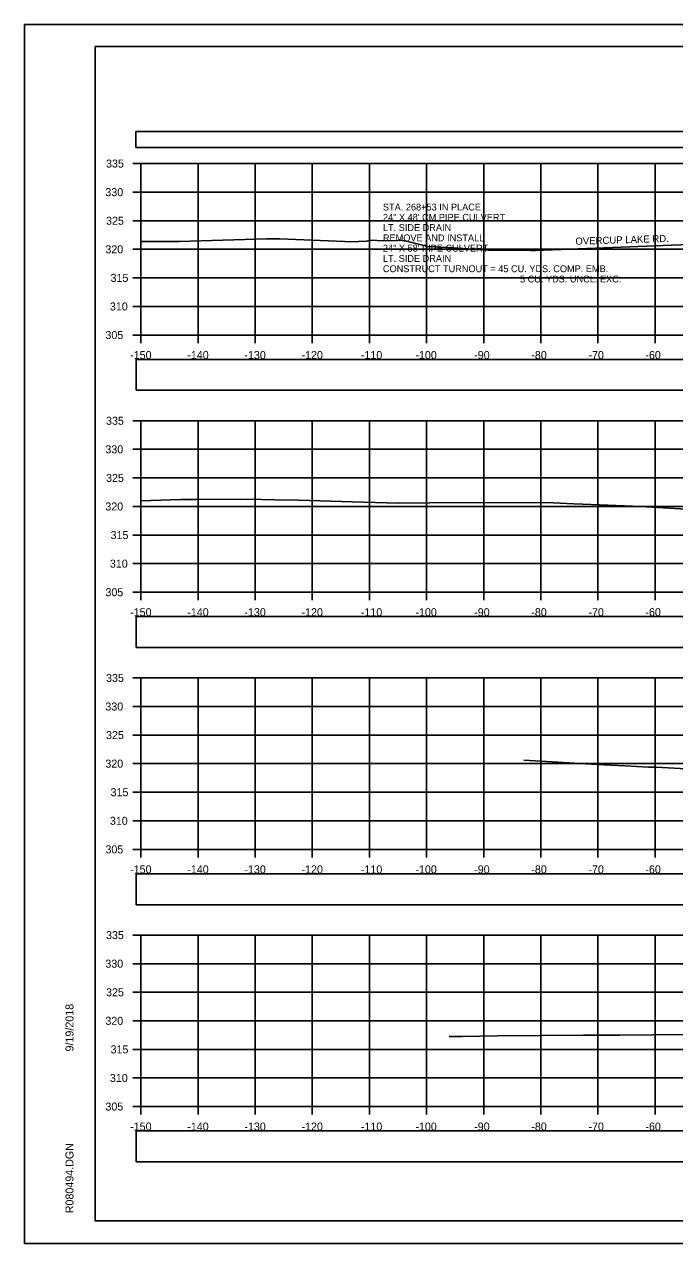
# Model space of a CAD drawing. Extents: x 1376273 to 1384221, y 378927 to 384592.
# Drawn here: x 1380021.2 to 1380135.1, y 383098.6 to 383311.9 of the extents above; entities that cross this region are included whole.
import ezdxf

# ---------------------------------------------------------------- set-up
doc = ezdxf.new("R2010")
doc.units = 0
for name, color, linetype in [('R_Axis', 7, 'Continuous'), ('R_Axis Annot', 7, 'Continuous'), ('R_Border', 7, 'Continuous'), ('R_Drive', 7, 'Continuous'), ('R_Exist Surface', 7, 'Continuous'), ('R_Grid', 7, 'Continuous'), ('R_No Plot', 7, 'Continuous')]:
    doc.layers.add(name, color=color, linetype=linetype)

msp = doc.modelspace()

# ---------------------------------------------------------------- linework, layer by layer
at = {"layer": 'R_Axis'}
for p, q in [((1380040.26, 383287.55), (1380041.66, 383287.55)), ((1380041.66, 383257.55), (1380041.66, 383287.55)), ((1380040.26, 383282.55), (1380041.66, 383282.55)), ((1380040.26, 383277.55), (1380041.66, 383277.55)), ((1380040.26, 383272.55), (1380041.66, 383272.55)), ((1380040.26, 383267.55), (1380041.66, 383267.55)), ((1380040.26, 383262.55), (1380041.66, 383262.55)), ((1380040.26, 383257.55), (1380041.66, 383257.55)), ((1380041.66, 383257.55), (1380341.66, 383257.55)), ((1380041.66, 383256.15), (1380041.66, 383257.55)), ((1380051.66, 383256.15), (1380051.66, 383257.55)), ((1380061.66, 383256.15), (1380061.66, 383257.55)), ((1380071.66, 383256.15), (1380071.66, 383257.55)), ((1380081.66, 383256.15), (1380081.66, 383257.55)), ((1380091.66, 383256.15), (1380091.66, 383257.55)), ((1380101.66, 383256.15), (1380101.66, 383257.55)), ((1380111.66, 383256.15), (1380111.66, 383257.55)), ((1380121.66, 383256.15), (1380121.66, 383257.55)), ((1380131.66, 383256.15), (1380131.66, 383257.55)), ((1380040.26, 383242.55), (1380041.66, 383242.55)), ((1380041.66, 383212.55), (1380041.66, 383242.55)), ((1380040.26, 383237.55), (1380041.66, 383237.55)), ((1380040.26, 383232.55), (1380041.66, 383232.55)), ((1380040.26, 383227.55), (1380041.66, 383227.55)), ((1380040.26, 383222.55), (1380041.66, 383222.55)), ((1380040.26, 383217.55), (1380041.66, 383217.55)), ((1380040.26, 383212.55), (1380041.66, 383212.55)), ((1380041.66, 383212.55), (1380341.66, 383212.55)), ((1380041.66, 383211.15), (1380041.66, 383212.55)), ((1380051.66, 383211.15), (1380051.66, 383212.55)), ((1380061.66, 383211.15), (1380061.66, 383212.55)), ((1380071.66, 383211.15), (1380071.66, 383212.55)), ((1380081.66, 383211.15), (1380081.66, 383212.55)), ((1380091.66, 383211.15), (1380091.66, 383212.55)), ((1380101.66, 383211.15), (1380101.66, 383212.55)), ((1380111.66, 383211.15), (1380111.66, 383212.55)), ((1380121.66, 383211.15), (1380121.66, 383212.55)), ((1380131.66, 383211.15), (1380131.66, 383212.55)), ((1380040.26, 383197.55), (1380041.66, 383197.55)), ((1380041.66, 383167.55), (1380041.66, 383197.55)), ((1380040.26, 383192.55), (1380041.66, 383192.55)), ((1380040.26, 383187.55), (1380041.66, 383187.55)), ((1380040.26, 383182.55), (1380041.66, 383182.55)), ((1380040.26, 383177.55), (1380041.66, 383177.55)), ((1380040.26, 383172.55), (1380041.66, 383172.55)), ((1380040.26, 383167.55), (1380041.66, 383167.55)), ((1380041.66, 383167.55), (1380341.66, 383167.55)), ((1380041.66, 383166.15), (1380041.66, 383167.55)), ((1380051.66, 383166.15), (1380051.66, 383167.55)), ((1380061.66, 383166.15), (1380061.66, 383167.55)), ((1380071.66, 383166.15), (1380071.66, 383167.55)), ((1380081.66, 383166.15), (1380081.66, 383167.55)), ((1380091.66, 383166.15), (1380091.66, 383167.55)), ((1380101.66, 383166.15), (1380101.66, 383167.55)), ((1380111.66, 383166.15), (1380111.66, 383167.55)), ((1380121.66, 383166.15), (1380121.66, 383167.55)), ((1380131.66, 383166.15), (1380131.66, 383167.55)), ((1380040.26, 383152.55), (1380041.66, 383152.55)), ((1380041.66, 383122.55), (1380041.66, 383152.55)), ((1380040.26, 383147.55), (1380041.66, 383147.55)), ((1380040.26, 383142.55), (1380041.66, 383142.55)), ((1380040.26, 383137.55), (1380041.66, 383137.55)), ((1380040.26, 383132.55), (1380041.66, 383132.55)), ((1380040.26, 383127.55), (1380041.66, 383127.55)), ((1380040.26, 383122.55), (1380041.66, 383122.55)), ((1380041.66, 383122.55), (1380341.66, 383122.55)), ((1380041.66, 383121.15), (1380041.66, 383122.55)), ((1380051.66, 383121.15), (1380051.66, 383122.55)), ((1380061.66, 383121.15), (1380061.66, 383122.55)), ((1380071.66, 383121.15), (1380071.66, 383122.55)), ((1380081.66, 383121.15), (1380081.66, 383122.55)), ((1380091.66, 383121.15), (1380091.66, 383122.55)), ((1380101.66, 383121.15), (1380101.66, 383122.55)), ((1380111.66, 383121.15), (1380111.66, 383122.55)), ((1380121.66, 383121.15), (1380121.66, 383122.55)), ((1380131.66, 383121.15), (1380131.66, 383122.55))]:
    msp.add_line(p, q, dxfattribs=at)
at = {"layer": 'R_Axis Annot'}
for points in [[(1380040.77, 383290.34), (1380342.57, 383290.34), (1380342.57, 383293.15), (1380040.77, 383293.15)], [(1380040.81, 383247.88), (1380342.5, 383247.88), (1380342.5, 383253.29), (1380040.81, 383253.29)], [(1380040.81, 383202.87), (1380342.5, 383202.87), (1380342.5, 383208.28), (1380040.81, 383208.28)], [(1380040.81, 383157.87), (1380342.5, 383157.87), (1380342.5, 383163.28), (1380040.81, 383163.28)], [(1380040.81, 383112.89), (1380342.5, 383112.89), (1380342.5, 383118.3), (1380040.81, 383118.3)]]:
    msp.add_lwpolyline(points, close=True, dxfattribs=at)
at = {"layer": 'R_Border'}
for p, q in [((1380033.66, 383308.01), (1380349.84, 383308.01)), ((1380033.66, 383102.55), (1380033.66, 383308.01)), ((1380033.66, 383102.55), (1380033.66, 383102.55)), ((1380349.84, 383102.55), (1380033.66, 383102.55))]:
    msp.add_line(p, q, dxfattribs=at)
at = {"layer": 'R_Exist Surface'}
for points in [[(1380041.66, 383273.9), (1380044.66, 383273.94), (1380048.35, 383273.93), (1380063.63, 383274.37), (1380064.07, 383274.38), (1380065.91, 383274.4), (1380077.34, 383273.91), (1380078.34, 383273.87), (1380081.13, 383273.99), (1380081.88, 383274.13), (1380084.14, 383274.01), (1380086.61, 383274.09), (1380086.92, 383274.13), (1380088.12, 383273.98), (1380091.87, 383273.03), (1380095.41, 383272.86), (1380102.52, 383272.4), (1380104.64, 383272.39), (1380109.94, 383272.35), (1380110.57, 383272.35), (1380110.76, 383272.35), (1380130.23, 383273.07), (1380134.48, 383273.3), (1380137.89, 383273.37)], [(1380041.66, 383228.51), (1380048.57, 383228.77), (1380051.37, 383228.77), (1380060.31, 383228.82), (1380065.16, 383228.73), (1380069.28, 383228.64), (1380078.64, 383228.34), (1380086.77, 383228.11), (1380092.25, 383228.21), (1380110.35, 383228.25), (1380113.85, 383228.17), (1380117.44, 383228.02), (1380123.44, 383227.8), (1380129.16, 383227.56), (1380139.04, 383226.95)], [(1380108.7, 383183.17), (1380121.52, 383182.43), (1380126.45, 383182.16), (1380130.53, 383181.95), (1380131.87, 383181.95), (1380146.62, 383181.13)], [(1380095.63, 383134.81), (1380097.85, 383134.78), (1380104.07, 383134.95), (1380119.15, 383135.02), (1380125.52, 383135.04), (1380142.92, 383135.2)]]:
    msp.add_lwpolyline(points, dxfattribs=at)
at = {"layer": 'R_Grid'}
for p, q in [((1380041.66, 383287.55), (1380341.66, 383287.55)), ((1380041.66, 383257.55), (1380041.66, 383287.55)), ((1380051.66, 383257.55), (1380051.66, 383287.55)), ((1380061.66, 383257.55), (1380061.66, 383287.55)), ((1380071.66, 383257.55), (1380071.66, 383287.55)), ((1380081.66, 383257.55), (1380081.66, 383287.55)), ((1380091.66, 383257.55), (1380091.66, 383287.55)), ((1380101.66, 383257.55), (1380101.66, 383287.55)), ((1380111.66, 383257.55), (1380111.66, 383287.55)), ((1380121.66, 383257.55), (1380121.66, 383287.55)), ((1380131.66, 383257.55), (1380131.66, 383287.55)), ((1380041.66, 383282.55), (1380341.66, 383282.55)), ((1380041.66, 383277.55), (1380341.66, 383277.55)), ((1380041.66, 383272.55), (1380341.66, 383272.55)), ((1380041.66, 383267.55), (1380341.66, 383267.55)), ((1380041.66, 383262.55), (1380341.66, 383262.55)), ((1380041.66, 383257.55), (1380341.66, 383257.55)), ((1380041.66, 383242.55), (1380341.66, 383242.55)), ((1380041.66, 383212.55), (1380041.66, 383242.55)), ((1380051.66, 383212.55), (1380051.66, 383242.55)), ((1380061.66, 383212.55), (1380061.66, 383242.55)), ((1380071.66, 383212.55), (1380071.66, 383242.55)), ((1380081.66, 383212.55), (1380081.66, 383242.55)), ((1380091.66, 383212.55), (1380091.66, 383242.55)), ((1380101.66, 383212.55), (1380101.66, 383242.55)), ((1380111.66, 383212.55), (1380111.66, 383242.55)), ((1380121.66, 383212.55), (1380121.66, 383242.55)), ((1380131.66, 383212.55), (1380131.66, 383242.55)), ((1380041.66, 383237.55), (1380341.66, 383237.55)), ((1380041.66, 383232.55), (1380341.66, 383232.55)), ((1380041.66, 383227.55), (1380341.66, 383227.55)), ((1380041.66, 383222.55), (1380341.66, 383222.55)), ((1380041.66, 383217.55), (1380341.66, 383217.55)), ((1380041.66, 383212.55), (1380341.66, 383212.55)), ((1380041.66, 383197.55), (1380341.66, 383197.55)), ((1380041.66, 383167.55), (1380041.66, 383197.55)), ((1380051.66, 383167.55), (1380051.66, 383197.55)), ((1380061.66, 383167.55), (1380061.66, 383197.55)), ((1380071.66, 383167.55), (1380071.66, 383197.55)), ((1380081.66, 383167.55), (1380081.66, 383197.55)), ((1380091.66, 383167.55), (1380091.66, 383197.55)), ((1380101.66, 383167.55), (1380101.66, 383197.55)), ((1380111.66, 383167.55), (1380111.66, 383197.55)), ((1380121.66, 383167.55), (1380121.66, 383197.55)), ((1380131.66, 383167.55), (1380131.66, 383197.55)), ((1380041.66, 383192.55), (1380341.66, 383192.55)), ((1380041.66, 383187.55), (1380341.66, 383187.55)), ((1380041.66, 383182.55), (1380341.66, 383182.55)), ((1380041.66, 383177.55), (1380341.66, 383177.55)), ((1380041.66, 383172.55), (1380341.66, 383172.55)), ((1380041.66, 383167.55), (1380341.66, 383167.55)), ((1380041.66, 383152.55), (1380341.66, 383152.55)), ((1380041.66, 383122.55), (1380041.66, 383152.55)), ((1380051.66, 383122.55), (1380051.66, 383152.55)), ((1380061.66, 383122.55), (1380061.66, 383152.55)), ((1380071.66, 383122.55), (1380071.66, 383152.55)), ((1380081.66, 383122.55), (1380081.66, 383152.55)), ((1380091.66, 383122.55), (1380091.66, 383152.55)), ((1380101.66, 383122.55), (1380101.66, 383152.55)), ((1380111.66, 383122.55), (1380111.66, 383152.55)), ((1380121.66, 383122.55), (1380121.66, 383152.55)), ((1380131.66, 383122.55), (1380131.66, 383152.55)), ((1380041.66, 383147.55), (1380341.66, 383147.55)), ((1380041.66, 383142.55), (1380341.66, 383142.55)), ((1380041.66, 383137.55), (1380341.66, 383137.55)), ((1380041.66, 383132.55), (1380341.66, 383132.55)), ((1380041.66, 383127.55), (1380341.66, 383127.55)), ((1380041.66, 383122.55), (1380341.66, 383122.55))]:
    msp.add_line(p, q, dxfattribs=at)
at = {"layer": 'R_No Plot'}
for p, q in [((1380021.26, 383311.9), (1380354.59, 383311.9)), ((1380021.26, 383098.57), (1380354.59, 383098.57))]:
    msp.add_line(p, q, dxfattribs=at)
for points in [[(1380021.25, 383311.9), (1380354.59, 383311.9), (1380354.59, 383098.57), (1380021.25, 383098.57)], [(1380267.58, 383308.01), (1380267.58, 383298.13), (1380303.31, 383298.13), (1380303.31, 383295.21), (1380326.51, 383295.21), (1380326.51, 383270.88), (1380349.84, 383270.88), (1380349.84, 383102.55), (1380033.66, 383102.55), (1380033.66, 383308.01)]]:
    msp.add_lwpolyline(points, close=True, dxfattribs=at)

# ---------------------------------------------------------------- texts
at = {"layer": 'R_Axis Annot'}
for s, height, p in [('335', 1.4, (1380035.55, 383286.85)), ('330', 1.4, (1380035.43, 383281.85)), ('STA. 268+53 IN PLACE', 1.2, (1380084.02, 383279.34)), ('325', 1.4, (1380035.55, 383276.85)), ('24" X 48\' CM PIPE CULVERT', 1.2, (1380084.02, 383277.55)), ('LT. SIDE DRAIN', 1.2, (1380084.02, 383275.75)), ('REMOVE AND INSTALL', 1.2, (1380084.02, 383273.95)), ('320', 1.4, (1380035.43, 383271.85)), ('24" X 58\' PIPE CULVERT', 1.2, (1380084.02, 383272.15)), ('CONSTRUCT TURNOUT = 45 CU. YDS. COMP. EMB.', 1.2, (1380084.02, 383268.55)), ('LT. SIDE DRAIN', 1.2, (1380084.02, 383270.35)), ('315', 1.4, (1380036.34, 383266.85)), ('5 CU. YDS. UNCL. EXC.', 1.2, (1380108.02, 383266.75)), ('310', 1.4, (1380036.22, 383261.85)), ('305', 1.4, (1380035.44, 383256.85)), ('-150', 1.4, (1380039.77, 383253.35)), ('-140', 1.4, (1380049.77, 383253.35)), ('-130', 1.4, (1380059.77, 383253.35)), ('-120', 1.4, (1380069.77, 383253.35)), ('-110', 1.4, (1380080.16, 383253.35)), ('-100', 1.4, (1380089.71, 383253.35)), ('-90', 1.4, (1380100, 383253.35)), ('-80', 1.4, (1380110, 383253.35)), ('-70', 1.4, (1380120, 383253.35)), ('-60', 1.4, (1380129.97, 383253.35)), ('335', 1.4, (1380035.55, 383241.85)), ('330', 1.4, (1380035.43, 383236.85)), ('325', 1.4, (1380035.55, 383231.85)), ('320', 1.4, (1380035.43, 383226.85)), ('315', 1.4, (1380036.34, 383221.85)), ('310', 1.4, (1380036.22, 383216.85)), ('305', 1.4, (1380035.44, 383211.85)), ('-150', 1.4, (1380039.77, 383208.35)), ('-140', 1.4, (1380049.77, 383208.35)), ('-130', 1.4, (1380059.77, 383208.35)), ('-120', 1.4, (1380069.77, 383208.35)), ('-110', 1.4, (1380080.16, 383208.35)), ('-100', 1.4, (1380089.71, 383208.35)), ('-90', 1.4, (1380100, 383208.35)), ('-80', 1.4, (1380110, 383208.35)), ('-70', 1.4, (1380120, 383208.35)), ('-60', 1.4, (1380129.97, 383208.35)), ('335', 1.4, (1380035.55, 383196.85)), ('330', 1.4, (1380035.43, 383191.85)), ('325', 1.4, (1380035.55, 383186.85)), ('320', 1.4, (1380035.43, 383181.85)), ('315', 1.4, (1380036.34, 383176.85)), ('310', 1.4, (1380036.22, 383171.85)), ('305', 1.4, (1380035.44, 383166.85)), ('-150', 1.4, (1380039.77, 383163.35)), ('-140', 1.4, (1380049.77, 383163.35)), ('-130', 1.4, (1380059.77, 383163.35)), ('-120', 1.4, (1380069.77, 383163.35)), ('-110', 1.4, (1380080.16, 383163.35)), ('-100', 1.4, (1380089.71, 383163.35)), ('-90', 1.4, (1380100, 383163.35)), ('-80', 1.4, (1380110, 383163.35)), ('-70', 1.4, (1380120, 383163.35)), ('-60', 1.4, (1380129.97, 383163.35)), ('335', 1.4, (1380035.55, 383151.85)), ('330', 1.4, (1380035.43, 383146.85)), ('325', 1.4, (1380035.55, 383141.85)), ('320', 1.4, (1380035.43, 383136.85)), ('315', 1.4, (1380036.34, 383131.85)), ('310', 1.4, (1380036.22, 383126.85)), ('305', 1.4, (1380035.44, 383121.85)), ('-150', 1.4, (1380039.77, 383118.35)), ('-140', 1.4, (1380049.77, 383118.35)), ('-130', 1.4, (1380059.77, 383118.35)), ('-120', 1.4, (1380069.77, 383118.35)), ('-110', 1.4, (1380080.16, 383118.35)), ('-100', 1.4, (1380089.71, 383118.35)), ('-90', 1.4, (1380100, 383118.35)), ('-80', 1.4, (1380110, 383118.35)), ('-70', 1.4, (1380120, 383118.35)), ('-60', 1.4, (1380129.97, 383118.35))]:
    msp.add_text(s, height=height, dxfattribs=at).set_placement(p)
at = {"layer": 'R_Border'}
for s, p in [('9/19/2018', (1380029.85, 383132.19)), ('R080494.DGN', (1380029.85, 383103.88))]:
    msp.add_text(s, height=1.4, rotation=90, dxfattribs=at).set_placement(p)
at = {"layer": 'R_Drive'}
msp.add_text('OVERCUP LAKE RD.', height=1.25, rotation=1.7647, dxfattribs=at).set_placement((1380117.74, 383273.34))

doc.saveas('drawing.dxf')
